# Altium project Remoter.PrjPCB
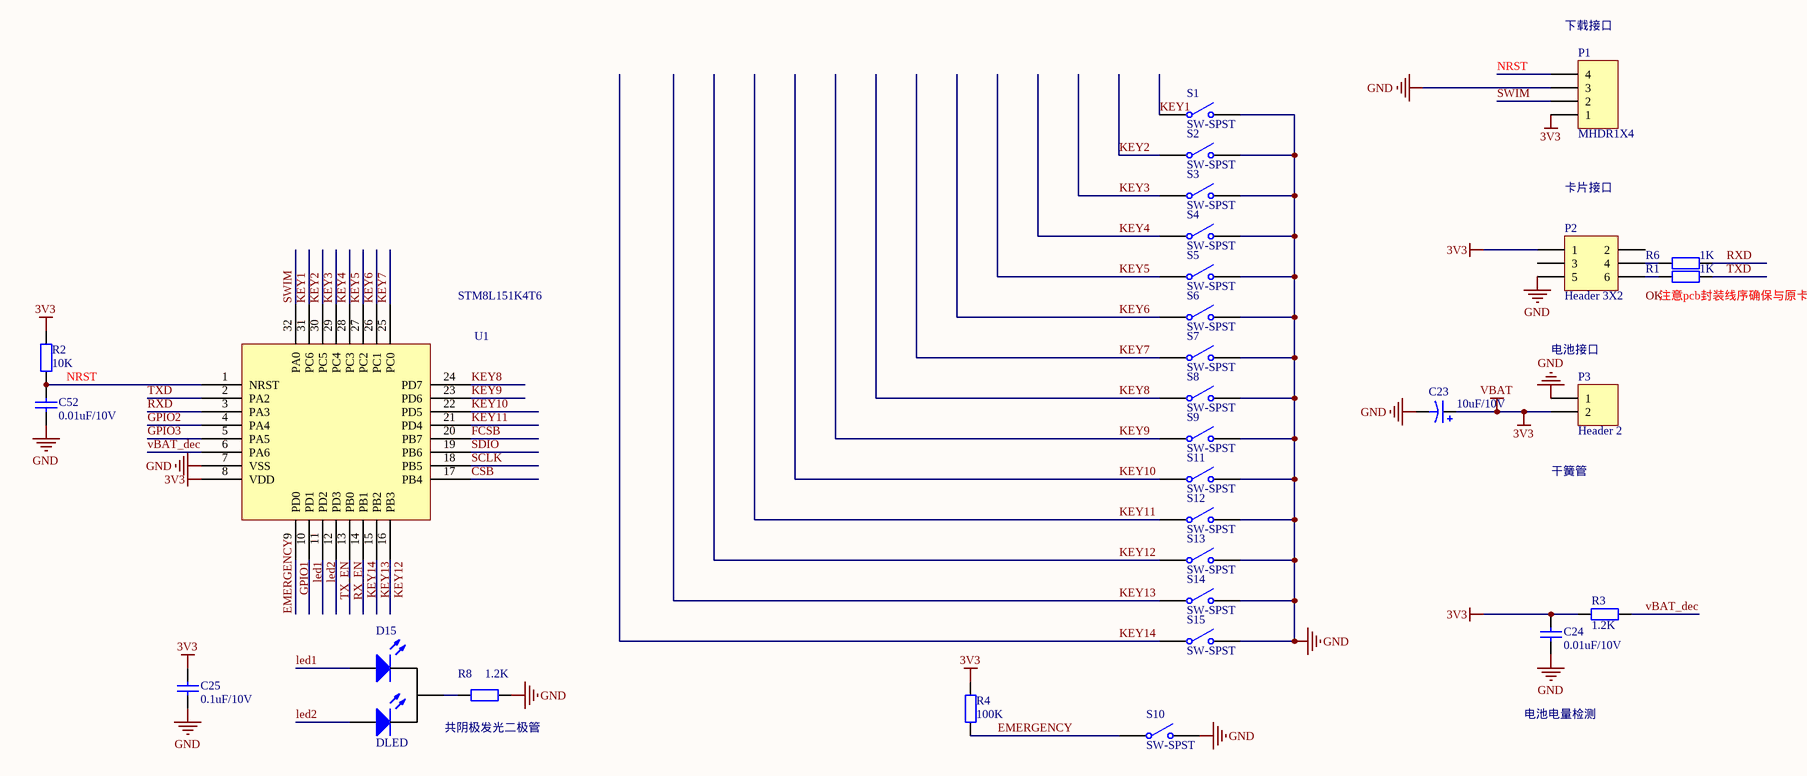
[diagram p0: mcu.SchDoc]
2 sheets, 70 parts. Net scope: global (net labels, ports and power ports of the same name join across sheets).
Sheets:
  mcu.SchDoc
  RF.SchDoc

## Sheet mcu.SchDoc
size A3

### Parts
C23  10uF/10V
C24  0.01uF/10V  [0603C]
C25  0.1uF/10V  [0603C]
C52  0.01uF/10V  [0603C]
D15  DLED
P1  MHDR1X4  [SIP4]
P2  Header 3X2
P3  Header 2
R1  1K  [0603R]
R2  10K  [0603R]
R3  1.2K  [0603R]
R4  100K  [0603R]
R6  1K  [0603R]
R8  1.2K  [0603R]
S1  SW-SPST
S2  SW-SPST
S3  SW-SPST
S4  SW-SPST
S5  SW-SPST
S6  SW-SPST
S7  SW-SPST
S8  SW-SPST
S9  SW-SPST
S10  SW-SPST
S11  SW-SPST
S12  SW-SPST
S13  SW-SPST
S14  SW-SPST
S15  SW-SPST
U1  STM8L151K4T6  [QFP80P900X900X245-32N]

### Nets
3V3: C23.1 C24.1 C25.1 P1.1 P2.1 P3.2 R2.2 R3.2 R4.1 U1.8(VDD)  [also labelled VBAT]
GND: C23.2 C24.2 C25.2 C52.2 P1.3 P2.5 P3.1 R8.1 S1.2(NO) S2.2(NO) S3.2(NO) S4.2(NO) S5.2(NO) S6.2(NO) S7.2(NO) S8.2(NO) S9.2(NO) S10.2(NO) S11.2(NO) S12.2(NO) S13.2(NO) S14.2(NO) S15.2(NO) U1.7(VSS)
CSB: U1.17(PB4)
EMERGENCY: R4.2 S10.1(COMMON) U1.9(PD0)  [also labelled GPIO1]
FCSB: U1.20(PB7)
GPIO2: U1.4(PA4)
GPIO3: U1.5(PA5)
KEY1: S1.1(COMMON) U1.31(PC6)
KEY2: S2.1(COMMON) U1.30(PC5)
KEY3: S3.1(COMMON) U1.29(PC4)
KEY4: S4.1(COMMON) U1.28(PC3)
KEY5: S5.1(COMMON) U1.27(PC2)
KEY6: S6.1(COMMON) U1.26(PC1)
KEY7: S7.1(COMMON) U1.25(PC0)
KEY8: S8.1(COMMON) U1.24(PD7)
KEY9: S9.1(COMMON) U1.23(PD6)
KEY10: S11.1(COMMON) U1.22(PD5)
KEY11: S12.1(COMMON) U1.21(PD4)
KEY12: S13.1(COMMON) U1.16(PB3)
KEY13: S14.1(COMMON) U1.15(PB2)
KEY14: S15.1(COMMON) U1.14(PB1)
led1: D15.1(A) U1.10(PD1)
led2: D15.3(A) U1.11(PD2)
NRST: C52.1 P1.4 R2.1 U1.1(NRST)
RX_EN: U1.13(PB0)
RXD: R6.1 U1.3(PA3)
SCLK: U1.18(PB5)
SDIO: U1.19(PB6)
SWIM: P1.2 U1.32(PA0)
TX_EN: U1.12(PD3)
TXD: R1.1 U1.2(PA2)
vBAT_dec: R3.1 U1.6(PA6)
NetD15_2: D15.2(K) R8.2
NetP2_4: P2.4 R6.2
NetP2_6: P2.6 R1.2

Not connected (* = marked no-connect by the designer): P2 2 3

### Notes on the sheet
- (near P1) 下载接口
- 卡片接口
- (near R1) 注意pcb封装线序确保与原卡片接口一致
- (near P3) 电池接口
- 干簧管
- 共阴极发光二极管
- 电池电量检测
- Labels drawn without touching a wire or pin: OK

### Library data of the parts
C23 = Cap Pol1: Polarized Capacitor (Radial); Value: 100pF
C24 C25 C52 = Cap: Capacitor; Value: 106
P1 = MHDR1X4: Header, 4-Pin
P2 = Header 3X2: Header, 3-Pin, Dual row
P3 = Header 2: Header, 2-Pin
R1-R4 R6 R8 = Res2: Resistor; Value: 10K/5%/1/8W
S1-S15 = SW-SPST: Single-Pole, Single-Throw Switch

## Sheet RF.SchDoc
size A3
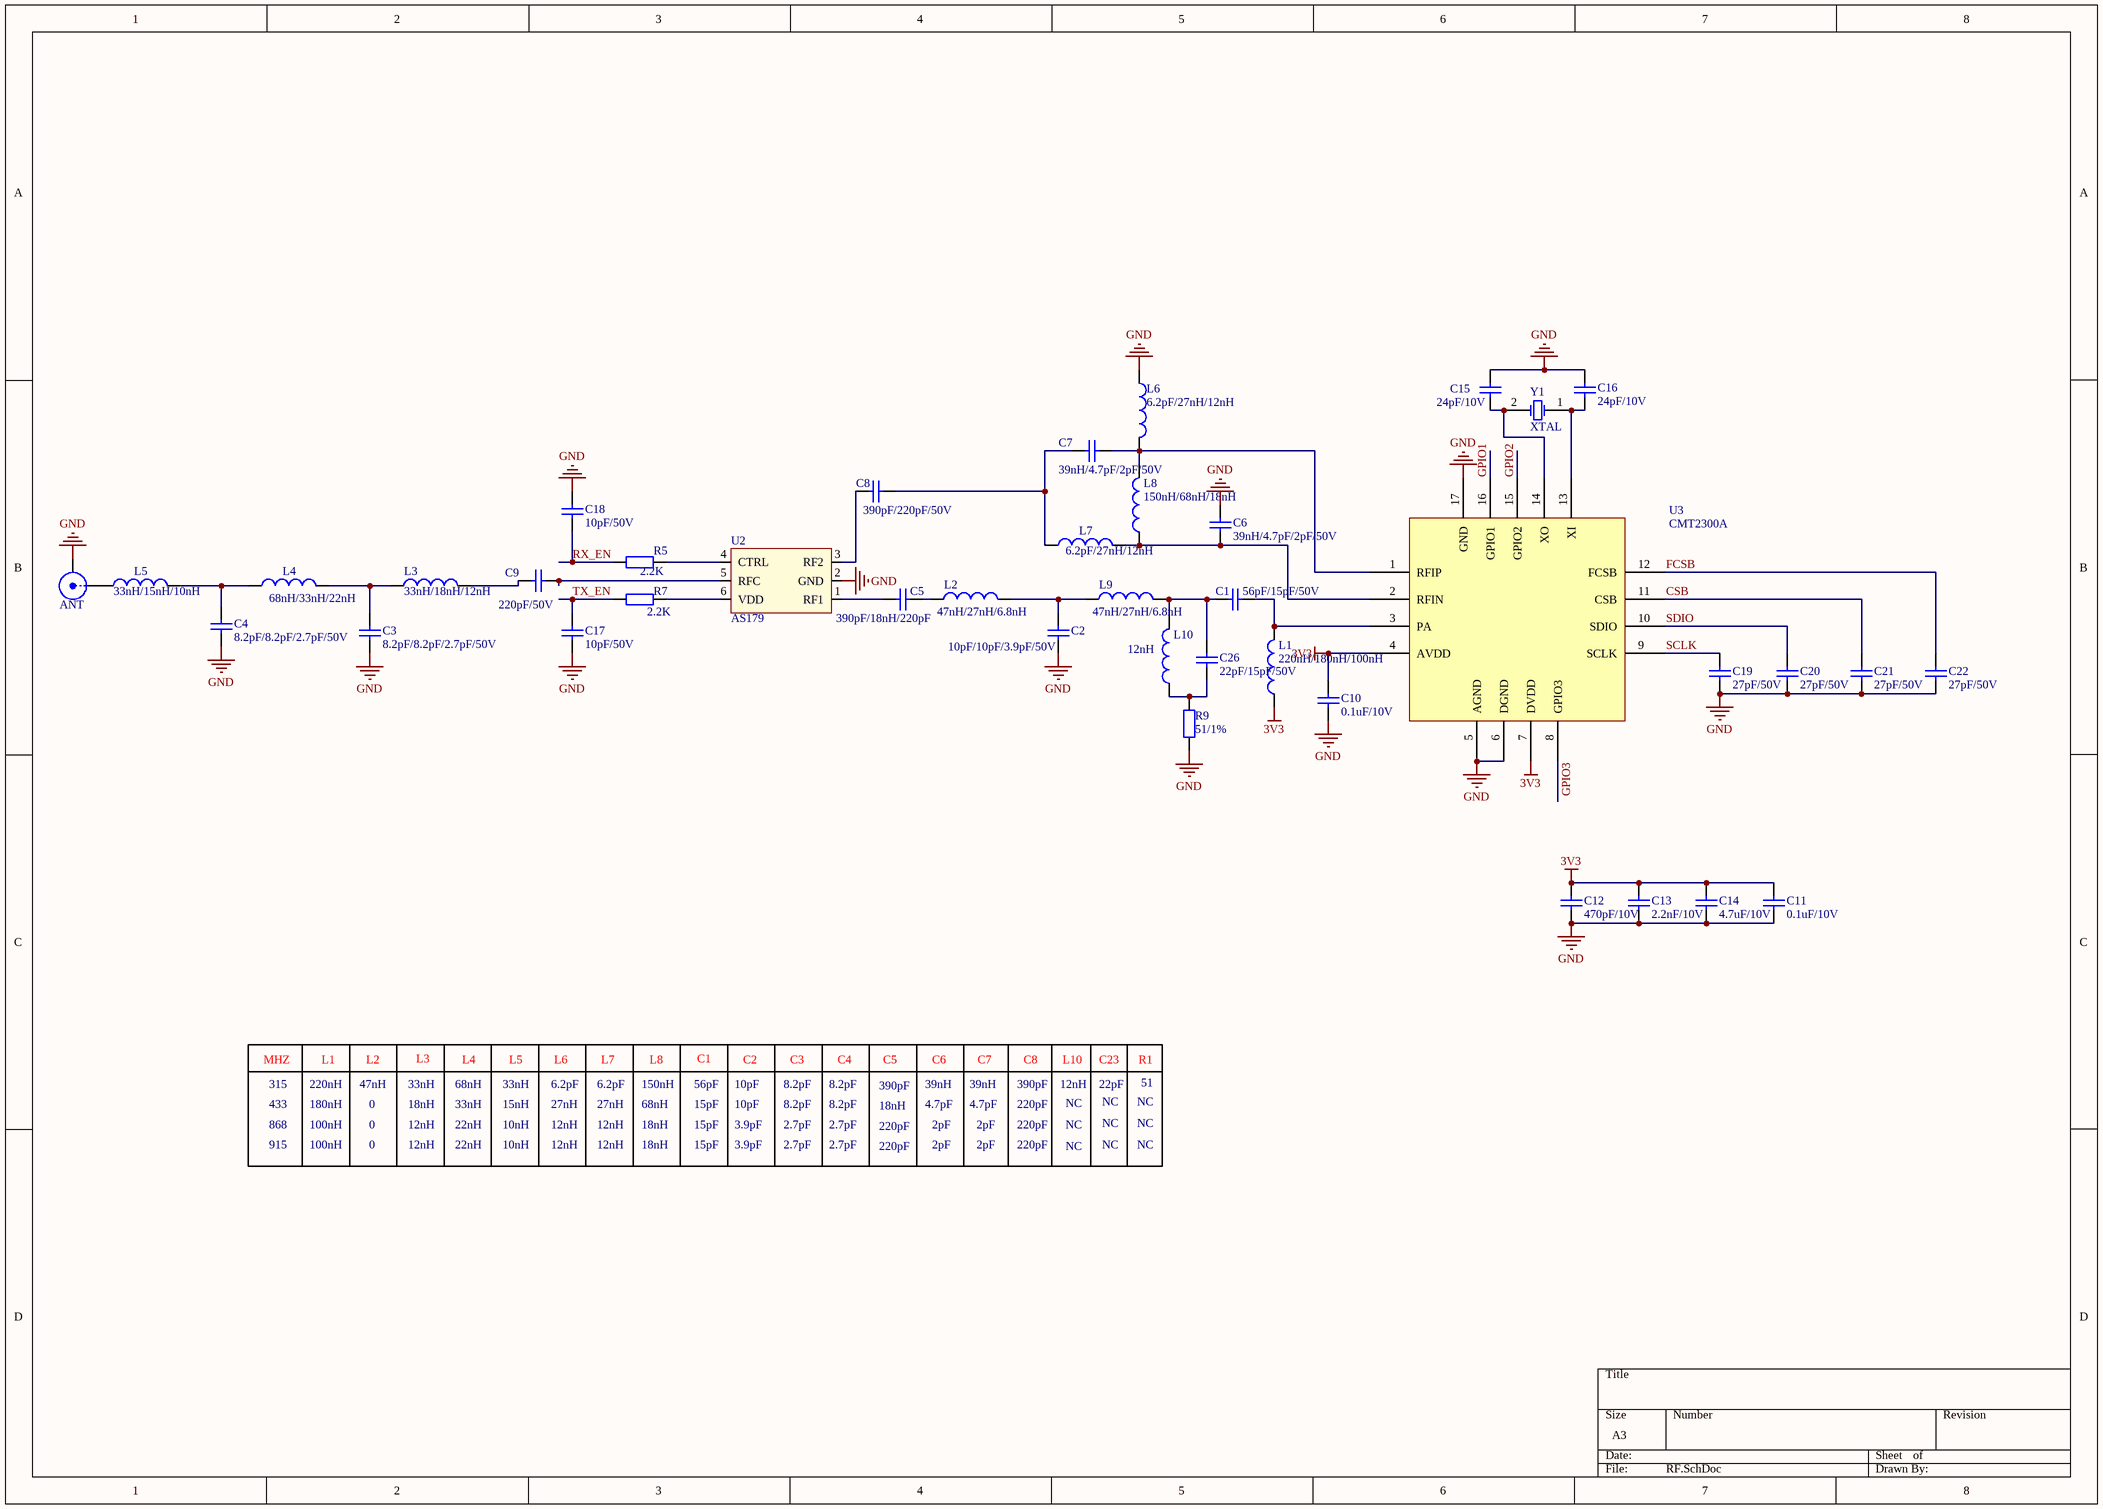
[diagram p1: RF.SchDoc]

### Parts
ANT  (no value)  [SMA Straight SMD]
C1  56pF/15pF/50V  [0603C]
C2  10pF/10pF/3.9pF/50V  [0603C]
C3  8.2pF/8.2pF/2.7pF/50V  [0603C]
C4  8.2pF/8.2pF/2.7pF/50V  [0603C]
C5  390pF/18nH/220pF  [0603C]
C6  39nH/4.7pF/2pF/50V  [0603C]
C7  39nH/4.7pF/2pF/50V  [0603C]
C8  390pF/220pF/50V  [0603C]
C9  220pF/50V  [0603C]
C10  0.1uF/10V  [0603C]
C11  0.1uF/10V  [0603C]
C12  470pF/10V  [0603C]
C13  2.2nF/10V  [0603C]
C14  4.7uF/10V  [0603C]
C15  24pF/10V  [0603C]
C16  24pF/10V  [0603C]
C17  10pF/50V  [0603C]
C18  10pF/50V  [0603C]
C19  27pF/50V  [0603C]
C20  27pF/50V  [0603C]
C21  27pF/50V  [0603C]
C22  27pF/50V  [0603C]
C26  22pF/15pF/50V  [0603C]
L1  220nH/180nH/100nH  [0603R]
L2  47nH/27nH/6.8nH  [0603R]
L3  33nH/18nH/12nH  [0603R]
L4  68nH/33nH/22nH  [0603R]
L5  33nH/15nH/10nH  [0603R]
L6  6.2pF/27nH/12nH  [0603R]
L7  6.2pF/27nH/12nH  [0603R]
L8  150nH/68nH/18nH  [0603R]
L9  47nH/27nH/6.8nH  [0603R]
L10  12nH  [0603R]
R5  2.2K  [0603R]
R7  2.2K  [0603R]
R9  51/1%  [0603R]
U2  AS179
U3  CMT2300A
Y1  XTAL  [BCY-W2/D3.1]

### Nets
3V3: C10.1 C11.1 C12.1 C13.1 C14.1 L1.1 U3.4(AVDD) U3.7(DVDD)
GND: ANT.2(GND) C2.1 C3.2 C4.2 C6.2 C10.2 C11.2 C12.2 C13.2 C14.2 C15.1 C16.1 C17.1 C18.2 C19.2 C20.2 C21.2 C22.2 L6.1 R9.2 U2.2(GND) U3.5(AGND) U3.6(DGND) U3.17(GND)
CSB: C21.1 U3.11(CSB)
FCSB: C22.1 U3.12(FCSB)
GPIO1: U3.16(GPIO1)  [project net EMERGENCY]
GPIO2: U3.15(GPIO2)
GPIO3: U3.8(GPIO3)
RX_EN: C18.1 R5.2
SCLK: C19.1 U3.9(SCLK)
SDIO: C20.1 U3.10(SDIO)
TX_EN: C17.2 R7.2
NetANT_1: ANT.1(Signal) L5.1
NetC1_1: C1.1 C26.2 L9.2 L10.2
NetC1_2: C1.2 L1.2 U3.3(PA)
NetC2_2: C2.2 L2.2 L9.1
NetC3_1: C3.1 L3.1 L4.2
NetC4_1: C4.1 L4.1 L5.2
NetC5_1: C5.1 U2.1(RF1)
NetC5_2: C5.2 L2.1
NetC6_1: C6.1 L7.2 L8.1 U3.2(RFIN)
NetC7_1: C7.1 C8.2 L7.1
NetC7_2: C7.2 L6.2 L8.2 U3.1(RFIP)
NetC8_1: C8.1 U2.3(RF2)
NetC9_1: C9.1 U2.5(RFC)
NetC9_2: C9.2 L3.2
NetC15_2: C15.2 U3.14(XO) Y1.2(OSC2)
NetC16_2: C16.2 U3.13(XI) Y1.1(OSC1)
NetC26_1: C26.1 L10.1 R9.1
NetR5_1: R5.1 U2.4(CTRL)
NetR7_1: R7.1 U2.6(VDD)

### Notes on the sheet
- MHZ
- 315
- 433
- 868
- 220nH
- 180nH
- 100nH
- L1
- 47nH
- L2
- 0
- 33nH
- 18nH
- 12nH
- L3
- 68nH
- 22nH
- L4
- 15nH
- 10nH
- L5
- 6.2pF
- 27nH
- L6
- L7
- 150nH
- L8
- 56pF
- 15pF
- C1
- 10pF
- 3.9pF
- C2
- 8.2pF
- 2.7pF
- C3
- C4
- 390pF
- C5
- 39nH
- 4.7pF
- C6
- 2pF
- C7
- 220pF
- C8
- L10
- NC
- C23
- 22pF
- R1
- 51
- 915

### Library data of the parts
ANT = SMA: SMA Straight Connector
C1-C22 C26 = Cap: Capacitor; Value: 106
L1-L10 = Inductor: Code_IEC: 1005; Value: 10mH
R5 R7 R9 = Res2: Resistor; Value: 10K/5%/1/8W
U2 = PE4259 RF Switch: PE4259 Peregrine RF Switch
Y1 = XTAL: Crystal Oscillator

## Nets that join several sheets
3V3: mcu (10 pins), RF (8 pins)
GND: mcu (24 pins), RF (24 pins)
CSB: mcu (U1.17), RF (C21.1 U3.11)
EMERGENCY: mcu (R4.2 S10.1 U1.9), RF (U3.16)
FCSB: mcu (U1.20), RF (C22.1 U3.12)
GPIO2: mcu (U1.4), RF (U3.15)
GPIO3: mcu (U1.5), RF (U3.8)
RX_EN: mcu (U1.13), RF (C18.1 R5.2)
SCLK: mcu (U1.18), RF (C19.1 U3.9)
SDIO: mcu (U1.19), RF (C20.1 U3.10)
TX_EN: mcu (U1.12), RF (C17.2 R7.2)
